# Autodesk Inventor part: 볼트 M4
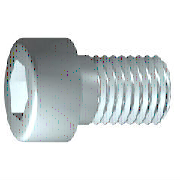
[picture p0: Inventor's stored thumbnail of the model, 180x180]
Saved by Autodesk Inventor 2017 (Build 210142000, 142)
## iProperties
IsCustomPart: 1
Created: 2012-02
Part Number: 볼트 M4
Material: 강철, 연강
Description: 6각머리 태핑 나사
Document SubType Name: Modeling
Standard: KS B 1003
Designer: mduedu
Standards Organization: KS
Language: ko-KR
Size Designation: M 4 x 10
Categories: <MemberInstance><Categories><Category DisplayName="조임쇠" InternalName="e4da775c-781d-43d5-af7c-5136215cf5a6" Mnemonic="FSTN"><Category DisplayName="볼트" InternalN
Density: 1 g/cm^3
Appearance: 강철
Author: mduedu
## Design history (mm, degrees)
sketch "스케치1"
  geometry: L1 (-1, 0)-(10, 0); L2 (10, 0)-(10, 2); L3 (10, 2)-(1.75, 2); L4 (1.75, 2)-(1.32, 2); L5 (1.32, 2)-(0, 2); L6 (0, 2)-(0, 3.5); L7 (0, 3.5)-(-4, 3.5); L8 (-4, 3.5)-(-4, 1.732); L9 (-4, 1.732)-(-2, 1.732); L10 (-2, 1.732)-(-1, 0); L11 (-6.8, 0)-(12.8, 0) reference; L12 (0, -0.7)-(0, 4.2) reference; L13 (1.75, 2)-(0, 2)
  constraints: 22 end point, 6 parallel, 2 collinear, 2 perpendicular, 1 horizontal, 1 point on line
  dimensions: "d1" = 8.25 distance from line of L3.end L2 (= GEL); "d2" = 0.42952 distance of L4.end L3.end (computed from GAL); "d3" = 4 distance between parallel lines of L8 L6 (= KOH); "d4" = 2 distance of L8.end L9.end (= INTI); "d5" = 60 deg angle of L10 L1; "d6" = 4 diameter of L3 L1 (= GD); "d7" = 4 diameter of L5 L1 (= BDM); "d8" = 3.4641 diameter of L9 L1 (= 1.1547 x SW); "d9" = 7 diameter of L7 L1 (= KOD); "d26" = 10 distance between parallel lines of L12 L2 (= NLG)
revolve "본체" sketch "스케치1" stored, may be unused: angle "d10" = 90 deg
sketch "스케치2"
  geometry: L1 (0, -4.9)-(0, 4.9) reference; L2 (-4.9, 0)-(4.9, 0) reference; L3 (1.732, 0)-(0.866, -1.5); L4 (0.866, -1.5)-(-0.866, -1.5); L5 (-0.866, -1.5)-(-1.732, 0); L6 (-1.732, 0)-(-0.866, 1.5); L7 (-0.866, 1.5)-(0.866, 1.5); L8 (0.866, 1.5)-(1.732, 0); 2 further points
  constraints: 12 end point, 1 coincident, 1 horizontal alignment, 1 point on line, 12 other
extrude "슬롯" join sketch "스케치2" stored distance "d11" = 10; taper "d12" = 0 deg
workplane "Work Plane1"
fillet "Fillet2" dims "d30" = 0.1 (= R)
body "Solid1"
fillet "모깎기1" dims "d17" = 0.4 (= RR)
feature "스레드" dims "d13" = 8.25 (= GEL), "d14" = 0
chamfer "모따기1" distance "d15" = 0.42941 (= -0.5 x SPD + 0.5 x GD); stored, may be unused: second distance "d16" = 0.42941 (= GUL), angle "d27" = 45 deg
other parameters: "GD" = 4 (= NND) [user parameter; used in 2 equation terms], "NLG" = 10 [user parameter; used in 1 equation term], "GEL" = 8.25 [user parameter; used in 2 equation terms], "KOD" = 7 [user parameter; used in 1 equation term], "KOH" = 4 [user parameter; used in 1 equation term], "INTI" = 2 [user parameter; used in 1 equation term], "GAL" = 0.42941 (= 0.61345 x PTC) [user parameter; used in 1 equation term], "GUL" = 0.42941 (= 0.61345 x PTC) [user parameter; used in 1 equation term], "BDM" = 4 (= NND) [user parameter; used in 1 equation term], "SW" = 3 [user parameter; used in 2 equation terms], "RR" = 0.4 [user parameter; used in 1 equation term], "SPD" = 3.14117 (= NND - 1.2269 x PTC) [user parameter; used in 1 equation term], "d19" = 0, "d28" = 0, "d29" = 0, "R" = 0.1 [user parameter; used in 1 equation term], "PHH" = 0.2 [user parameter], "GD1" = 3.14117 (= THREADDIA - 1.2269 x PTC) [user parameter], "THREADDIA" = 4 [user parameter; used in 1 equation term], "FAWI" = 45 deg [user parameter], "TPU" = 14.28571 (computed from PTC) [user parameter], "PTC" = 0.7 [user parameter; used in 5 equation terms], "NND" = 4 [user parameter; used in 3 equation terms], "TOA" = 30 deg [user parameter], "E0" = 3.465 (= 1.155 x SW) [user parameter]
